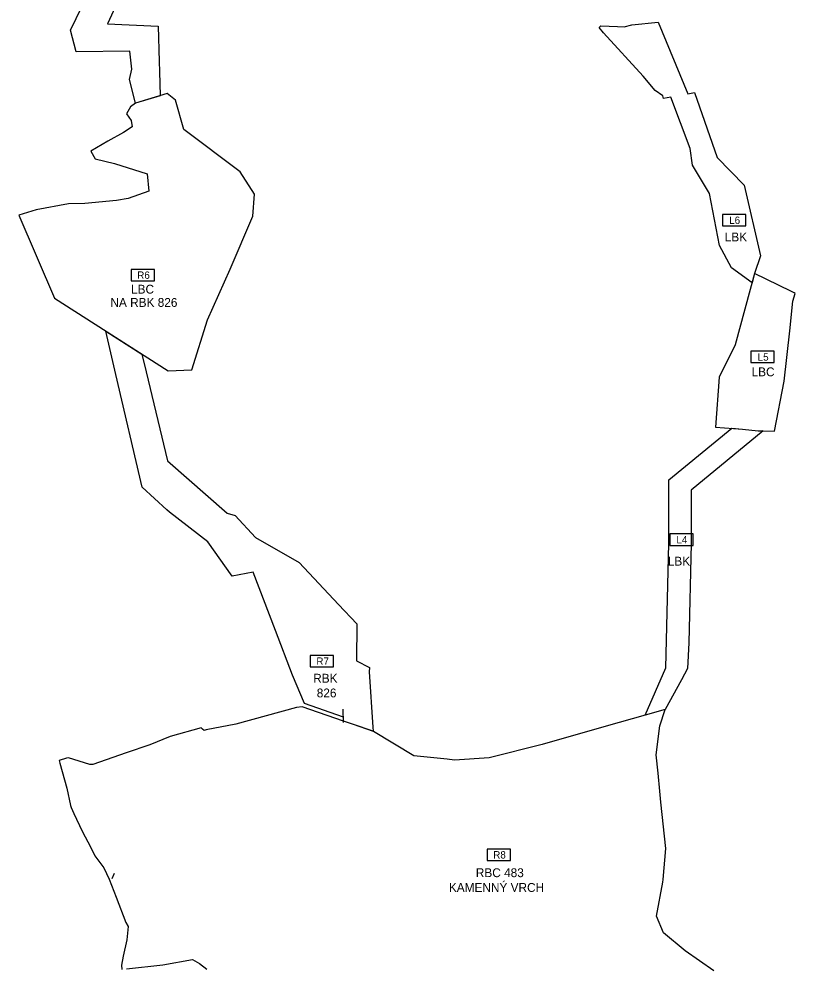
# Model space of a CAD drawing. Extents: x -546680 to -530218, y -1046521 to -1035695.
# Drawn here: x -541606 to -540553, y -1040976 to -1039689 of the extents above; entities that cross this region are included whole.
import ezdxf

# ---------------------------------------------------------------- set-up
doc = ezdxf.new("R2010")
doc.units = 0
for name, color, linetype in [('Vrstva 1', 7, 'Continuous'), ('Vrstva 16', 7, 'Continuous'), ('Vrstva 3', 7, 'Continuous'), ('Vrstva 30', 7, 'Continuous'), ('Vrstva 32', 7, 'Continuous'), ('Vrstva 33', 7, 'Continuous'), ('Vrstva 54', 7, 'Continuous'), ('Vrstva 82', 7, 'Continuous')]:
    doc.layers.add(name, color=color, linetype=linetype)

msp = doc.modelspace()

# ---------------------------------------------------------------- linework, layer by layer
at = {"layer": 'Vrstva 1'}
msp.add_line((-541165.6, -1040644.1), (-541166.2, -1040626.2), dxfattribs=at)
for points in [[(-541479.1, -1039585.5), (-541441.9, -1039599), (-541486, -1039695.6), (-541417.4, -1039699), (-541415.9, -1039747.1)], [(-541453, -1039757.1), (-541455.7, -1039732.7), (-541528.6, -1039734), (-541536.3, -1039704.6), (-541497.1, -1039623)], [(-541415.9, -1039747.1), (-541415.5, -1039760.6)], [(-541456.5, -1039771.5), (-541453, -1039757.1)], [(-541415.5, -1039760.6), (-541414.6, -1039793.3), (-541448.3, -1039803.6), (-541456.5, -1039771.5)], [(-541165.9, -1040636.8), (-541218.6, -1040618.3), (-541235.1, -1040580.1), (-541258.1, -1040519.5), (-541288.2, -1040439.9), (-541316.9, -1040445.7), (-541350.1, -1040399), (-541401.9, -1040358.6), (-541405.8, -1040355.7), (-541439.2, -1040324.8), (-541474.8, -1040171.6), (-541488.5, -1040112.9), (-541439.6, -1040144.2), (-541433.7, -1040168.3), (-541404.5, -1040289.1), (-541323.6, -1040360), (-541312.7, -1040363.1), (-541285.3, -1040393), (-541225.8, -1040427.1), (-541172.5, -1040483.8), (-541147.5, -1040510.4), (-541148, -1040560.7), (-541130.4, -1040569.3), (-541131, -1040575.4), (-541125.9, -1040650.7), (-541125.7, -1040656), (-541152, -1040647), (-541165.7, -1040642.3), (-541165.9, -1040636.8)]]:
    msp.add_lwpolyline(points, dxfattribs=at)
at = {"layer": 'Vrstva 16'}
for points in [[(-540663.1, -1040981.3), (-540701.9, -1040954.1), (-540731.5, -1040929.6), (-540740.7, -1040906.9), (-540732.4, -1040860.8), (-540732, -1040857.1), (-540728.2, -1040815.2), (-540735.1, -1040752.1), (-540736.5, -1040737.2), (-540738.7, -1040712.9), (-540741.2, -1040688.2), (-540736.1, -1040648.6), (-540729.2, -1040626.7), (-540756.3, -1040634.3), (-540809, -1040649), (-540896, -1040674), (-540968, -1040692), (-541015.2, -1040695.2), (-541025.2, -1040694.1), (-541070.4, -1040689.6), (-541125, -1040656.3), (-541152, -1040647), (-541166, -1040642.2), (-541222, -1040623), (-541229.8, -1040623.8), (-541312, -1040646.4), (-541352.1, -1040654.3), (-541355.1, -1040655.1), (-541357, -1040653.3), (-541359.2, -1040651.3), (-541400.9, -1040663.2), (-541428.9, -1040674.3), (-541460.7, -1040685.5), (-541506, -1040701.4), (-541510.3, -1040701.4), (-541539, -1040692), (-541541.8, -1040692.8), (-541551.9, -1040695.7), (-541550.8, -1040699.6), (-541541.4, -1040733.1), (-541536.3, -1040757), (-541535.7, -1040759.7), (-541531.8, -1040767.9), (-541520.5, -1040791.5), (-541508.8, -1040813.8), (-541503.5, -1040825.3), (-541491.3, -1040841.6), (-541484.1, -1040856.7), (-541474.3, -1040881.1), (-541461.4, -1040915.8), (-541458.3, -1040921.1), (-541460.1, -1040939.4), (-541464.7, -1040961.2), (-541467.2, -1040973.5), (-541466.9, -1040979.4)], [(-541476.9, -1040849.3), (-541480.1, -1040856.4)], [(-541460.4, -1040978.7), (-541410.9, -1040973.2), (-541370.6, -1040966), (-541361.4, -1040971.4), (-541351.5, -1040979)]]:
    msp.add_lwpolyline(points, dxfattribs=at)
at = {"layer": 'Vrstva 30'}
for points in [[(-541210.9, -1040553.1), (-541210.9, -1040568.6), (-541179.2, -1040568.6), (-541179.2, -1040553.1), (-541210.9, -1040553.1)], [(-540970.8, -1040816), (-540970.8, -1040831.6), (-540939.1, -1040831.6), (-540939.1, -1040816), (-540970.8, -1040816)]]:
    msp.add_lwpolyline(points, dxfattribs=at)
at = {"layer": 'Vrstva 32'}
for points in [[(-541306.1, -1039896.5), (-541382.4, -1039839.1), (-541393.7, -1039799.2), (-541405.3, -1039790.4), (-541448.3, -1039803.6), (-541454.8, -1039808.4), (-541460.3, -1039818.1), (-541454.1, -1039827.2), (-541452.7, -1039835.8), (-541464.4, -1039843.4), (-541485.8, -1039854.9), (-541509, -1039868.7), (-541503, -1039879.2), (-541476.8, -1039885.6), (-541432.3, -1039899.4)], [(-541403.8, -1040167), (-541371.5, -1040165.6), (-541350.4, -1040097.4), (-541319.8, -1040028.8), (-541288.9, -1039956.9), (-541286.8, -1039926.8), (-541306.1, -1039896.5)], [(-541432.3, -1039899.4), (-541429.9, -1039923.1)], [(-541429.9, -1039923.1), (-541458.2, -1039933.1), (-541474.1, -1039935.7), (-541517, -1039939.8), (-541539.3, -1039940.2), (-541583.1, -1039948.1), (-541606.4, -1039955.7), (-541558.2, -1040068.4), (-541403.8, -1040167)], [(-540567.6, -1040180.7), (-540559.8, -1040112.4), (-540555.8, -1040072.3), (-540552.8, -1040061.7), (-540554, -1040061), (-540558.6, -1040058.9), (-540607.8, -1040034.9), (-540634.2, -1040131.5), (-540655.9, -1040175.4)], [(-540655.9, -1040175.4), (-540660.9, -1040243.1), (-540624.2, -1040246), (-540602.9, -1040248.1)], [(-540580.6, -1040248.7), (-540567.6, -1040180.7)], [(-540602.9, -1040248.1), (-540580.6, -1040248.7)]]:
    msp.add_lwpolyline(points, dxfattribs=at)
at = {"layer": 'Vrstva 33'}
for points in [[(-540611.2, -1040047.4), (-540639.2, -1040026.9), (-540655.4, -1039996.5), (-540668.8, -1039925.9), (-540692.2, -1039887.8), (-540695.1, -1039865), (-540721.6, -1039795.5), (-540731.5, -1039797.3), (-540732.3, -1039793.4), (-540742.8, -1039786.4), (-540758.8, -1039767), (-540812.6, -1039707.9), (-540818.9, -1039700.6), (-540816.4, -1039698.7), (-540793.8, -1039699.6), (-540784.6, -1039699.7), (-540774.4, -1039697.3), (-540738.5, -1039693.5), (-540698.4, -1039791), (-540689.2, -1039789), (-540658.6, -1039877.4), (-540621.9, -1039914.8), (-540599.8, -1040010.8), (-540607.8, -1040034.9), (-540611.2, -1040047.4)], [(-540638.8, -1040244.8), (-540624.2, -1040246), (-540602.9, -1040248.1), (-540595.9, -1040248.3), (-540694, -1040329), (-540694, -1040401), (-540697, -1040536), (-540698.7, -1040571.1), (-540707, -1040586.2), (-540729.2, -1040626.7), (-540756.3, -1040634.3), (-540728, -1040570), (-540724, -1040401), (-540724, -1040315), (-540638.8, -1040244.8)]]:
    msp.add_lwpolyline(points, dxfattribs=at)
at = {"layer": 'Vrstva 54'}
for points in [[(-540651.1, -1039954.6), (-540651.1, -1039970.1), (-540619.4, -1039970.1), (-540619.4, -1039954.6), (-540651.1, -1039954.6)], [(-541454, -1040029.2), (-541454, -1040044.7), (-541422.3, -1040044.7), (-541422.3, -1040029.2), (-541454, -1040029.2)], [(-540612.6, -1040140.2), (-540612.6, -1040155.7), (-540580.9, -1040155.7), (-540580.9, -1040140.2), (-540612.6, -1040140.2)], [(-540722.7, -1040388.3), (-540722.7, -1040403.8), (-540691, -1040403.8), (-540691, -1040388.3), (-540722.7, -1040388.3)]]:
    msp.add_lwpolyline(points, dxfattribs=at)

# ---------------------------------------------------------------- texts
at = {"layer": 'Vrstva 3'}
for s, p in [('LBK', (-540648.2, -1039991.1)), ('LBC', (-541454.2, -1040062)), ('NA RBK 826', (-541482.2, -1040080)), ('LBC', (-540611.8, -1040174.2)), ('LBK', (-540725.5, -1040431.2)), ('RBK', (-541206.9, -1040590.1)), ('826', (-541202.1, -1040610.1)), ('RBC 483', (-540986.1, -1040854.1)), ('KAMENNÝ VRCH', (-541022.7, -1040874.1))]:
    msp.add_text(s, height=12, dxfattribs=at).set_placement(p)
at = {"layer": 'Vrstva 54'}
for s, p in [('L6', (-540642.2, -1039967.4)), ('R6', (-541445.8, -1040041.9)), ('L5', (-540603.5, -1040153)), ('L4', (-540713.8, -1040401))]:
    msp.add_text(s, height=10, dxfattribs=at).set_placement(p)
at = {"layer": 'Vrstva 82'}
for s, p in [('R7', (-541202.6, -1040565.9)), ('R8', (-540962.5, -1040828.8))]:
    msp.add_text(s, height=10, dxfattribs=at).set_placement(p)

doc.saveas('drawing.dxf')
